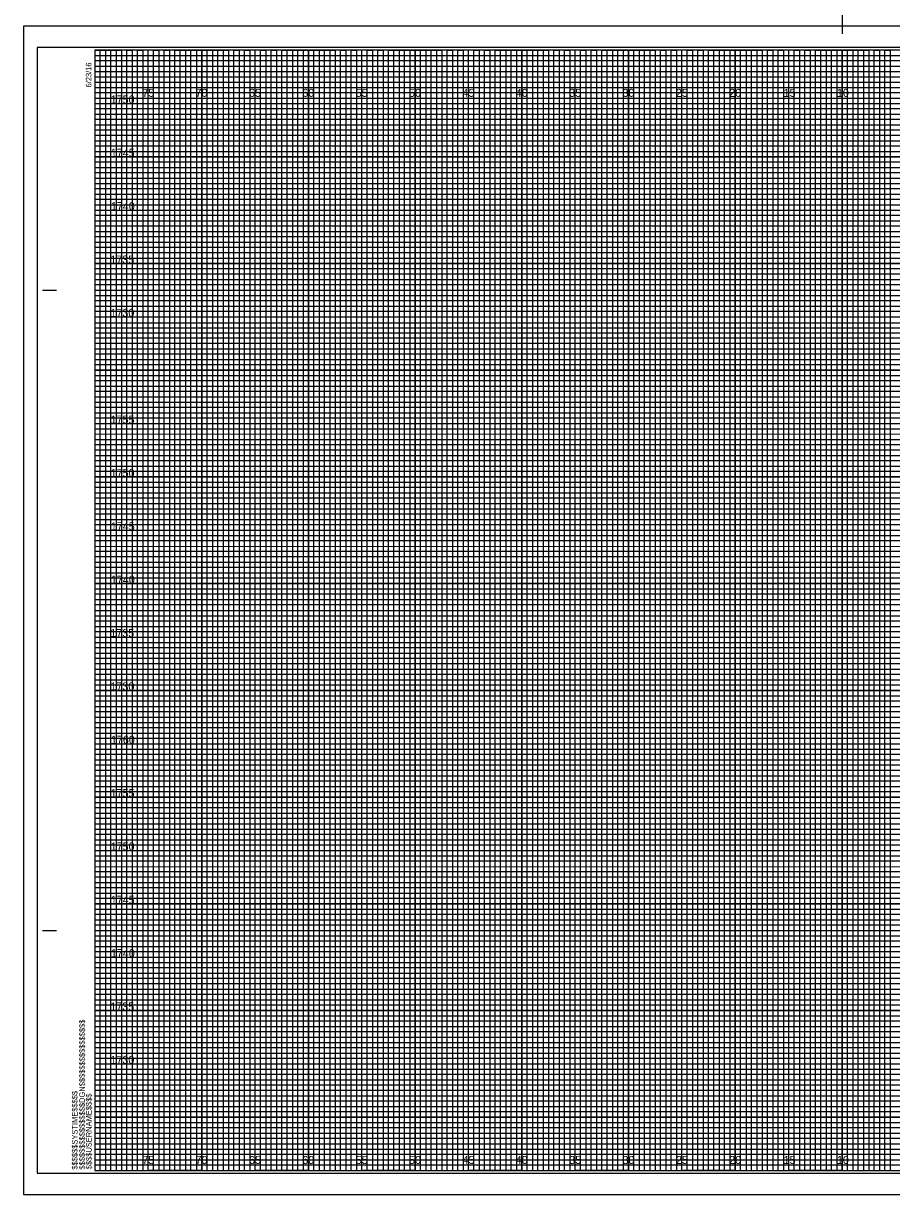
# Model space of a CAD drawing. Extents: x -7 to 162, y -2 to 327.
# Drawn here: x -6.7 to 74.6, y -2.3 to 107.5 of the extents above; entities that cross this region are included whole.
import ezdxf

# ---------------------------------------------------------------- set-up
doc = ezdxf.new("R2010")
doc.units = 0
for name, color, linetype in [('Prop XS Elevation Labels', 7, 'Continuous'), ('Prop XS Offset Labels', 7, 'Continuous'), ('Scratch_Level_5', 7, 'Continuous'), ('Sheet Cross Section CELL', 7, 'Continuous'), ('Sheet Cross Section Grid Major CELL', 7, 'Continuous'), ('Sheet Cross Section Grid Middle CELL', 7, 'Continuous'), ('Sheet Cross Section Grid Minor 1 CELL', 7, 'Continuous'), ('Sheet Cross Section Grid Minor 2 CELL', 7, 'Continuous'), ('Sheet Cutting Line CELL', 7, 'Continuous'), ('Sheet DOT Grid CELL', 7, 'Continuous'), ('Sheet Plot Border Inside CELL', 7, 'Continuous'), ('Sheet Plot Border Outside CELL', 7, 'Continuous')]:
    doc.layers.add(name, color=color, linetype=linetype)

msp = doc.modelspace()

# ---------------------------------------------------------------- linework, layer by layer
at = {"layer": 'Scratch_Level_5'}
msp.add_line((70, 176.62), (70, 106.52), dxfattribs=at)
at = {"layer": 'Sheet Cross Section CELL'}
for p, q in [((-4.9, 82.5), (-3.65, 82.5)), ((-4.85, 82.5), (-3.6, 82.5)), ((-4.9, 22.5), (-3.65, 22.5)), ((-4.85, 22.5), (-3.6, 22.5)), ((0, 0), (0, 0)), ((0, 0), (0, 0)), ((0, 0), (0, 0)), ((0, 0), (0, 0)), ((0, 0), (0, 0)), ((0, 0), (0, 0)), ((0, 0), (0, 0))]:
    msp.add_line(p, q, dxfattribs=at)
msp.add_lwpolyline([(160, 105), (0, 105), (0, 0), (160, 0)], close=True, dxfattribs=at)
at = {"layer": 'Sheet Cross Section Grid Major CELL'}
for p, q in [((5, 105), (0, 105)), ((5, 0), (5, 105)), ((15, 105), (10, 105)), ((10, 105), (10, 0)), ((15, 0), (15, 105)), ((25, 105), (20, 105)), ((20, 105), (20, 0)), ((25, 0), (25, 105)), ((35, 105), (30, 105)), ((30, 105), (30, 0)), ((35, 0), (35, 105)), ((45, 105), (40, 105)), ((40, 105), (40, 0)), ((45, 0), (45, 105)), ((55, 105), (50, 105)), ((50, 105), (50, 0)), ((55, 0), (55, 105)), ((65, 105), (60, 105)), ((60, 105), (60, 0)), ((65, 0), (65, 105)), ((75, 105), (70, 105)), ((70, 105), (70, 0)), ((10, 0), (5, 0)), ((20, 0), (15, 0)), ((30, 0), (25, 0)), ((40, 0), (35, 0)), ((50, 0), (45, 0)), ((60, 0), (55, 0)), ((70, 0), (65, 0))]:
    msp.add_line(p, q, dxfattribs=at)
for points in [[(0, 100), (160, 100), (160, 95), (0, 95)], [(0, 90), (160, 90), (160, 85), (0, 85)], [(0, 80), (160, 80), (160, 75), (0, 75)], [(0, 70), (160, 70), (160, 65), (0, 65)], [(0, 60), (160, 60), (160, 55), (0, 55)], [(0, 50), (160, 50), (160, 45), (0, 45)], [(0, 40), (160, 40), (160, 35), (0, 35)], [(0, 30), (160, 30), (160, 25), (0, 25)], [(0, 20), (160, 20), (160, 15), (0, 15)], [(0, 10), (160, 10), (160, 5), (0, 5)]]:
    msp.add_lwpolyline(points, dxfattribs=at)
at = {"layer": 'Sheet Cross Section Grid Middle CELL'}
for points in [[(0, 105), (2.5, 105), (2.5, 0), (7.5, 0), (7.5, 105), (12.5, 105), (12.5, 0), (17.5, 0), (17.5, 105), (22.5, 105), (22.5, 0), (27.5, 0), (27.5, 105), (32.5, 105), (32.5, 0), (37.5, 0), (37.5, 105), (42.5, 105), (42.5, 0), (47.5, 0), (47.5, 105), (52.5, 105), (52.5, 0), (57.5, 0), (57.5, 105), (62.5, 105), (62.5, 0), (67.5, 0), (67.5, 105), (72.5, 105), (72.5, 0), (77.5, 0)], [(0, 102.5), (137.5, 102.5)], [(0, 92.5), (160, 92.5), (160, 97.5), (0, 97.5)], [(0, 82.5), (160, 82.5), (160, 87.5), (0, 87.5)], [(0, 72.5), (160, 72.5), (160, 77.5), (0, 77.5)], [(0, 62.5), (160, 62.5), (160, 67.5), (0, 67.5)], [(0, 52.5), (160, 52.5), (160, 57.5), (0, 57.5)], [(0, 42.5), (160, 42.5), (160, 47.5), (0, 47.5)], [(0, 32.5), (160, 32.5), (160, 37.5), (0, 37.5)], [(0, 22.5), (160, 22.5), (160, 27.5), (0, 27.5)], [(0, 12.5), (160, 12.5), (160, 17.5), (0, 17.5)], [(0, 2.5), (160, 2.5), (160, 7.5), (0, 7.5)]]:
    msp.add_lwpolyline(points, dxfattribs=at)
at = {"layer": 'Sheet Cross Section Grid Minor 1 CELL'}
for p, q in [((0, 104.5), (130, 104.5)), ((130, 103.99), (0, 103.99)), ((0, 103.99), (0, 103.5)), ((0, 103.5), (130, 103.5)), ((130, 102.95), (0, 102.95)), ((0, 102.95), (0, 102)), ((0, 102), (160, 102))]:
    msp.add_line(p, q, dxfattribs=at)
for points in [[(0, 101.5), (135, 101.5), (160, 101.5), (160, 101), (0, 101)], [(0, 100.5), (160, 100.5), (160, 99.5), (0, 99.5)], [(0, 99), (160, 99), (160, 98.5), (0, 98.49)], [(0, 98), (160, 98), (160, 97), (0, 97)], [(0, 96.5), (160, 96.5), (160, 96), (0, 96)], [(0, 95.5), (160, 95.5), (160, 94.5), (0, 94.5)], [(0, 94), (160, 94), (160, 93.5), (0, 93.5)], [(0, 93), (160, 93), (160, 92), (0, 92)], [(0, 91.5), (160, 91.5), (160, 91), (0, 91)], [(0, 90.5), (160, 90.5), (160, 89.5), (0, 89.5)], [(0, 89), (160, 89), (160, 88.5), (0, 88.5)], [(0, 88), (160, 88), (160, 86.98), (160, 86.5), (160, 86), (0, 86)], [(0, 87), (160, 87), (160, 86.5), (0, 86.5)], [(0, 85.5), (160, 85.5), (160, 84.5), (0, 84.52)], [(0, 84.52), (160, 84.5), (160, 84), (0, 84)], [(0, 83.5), (160, 83.5), (160, 83), (0, 83)], [(0, 82), (160, 82), (160, 81.5), (0, 81.5)], [(0, 81), (160, 81), (160, 80.5), (0, 80.5)], [(-0.04, 79.45), (160, 79.45), (160, 78.94), (-0.04, 78.94)], [(0, 78.5), (160, 78.5), (160, 78), (0, 78)], [(0, 77), (160, 77), (160, 76.5), (0, 76.5)], [(0, 76), (160, 76), (160, 75.5), (0, 75.5)], [(0, 74.5), (160, 74.5), (160, 74), (0, 74)], [(0, 73.5), (160, 73.5), (160, 73), (0, 73)], [(0, 72), (160, 72), (160, 71.5), (0, 71.5)], [(0, 71), (160, 71), (160, 70.5), (0, 70.5)], [(0, 69.5), (160, 69.5), (160, 68.99), (0, 69)], [(0, 68.5), (160, 68.5), (160, 68), (0, 68)], [(0, 67), (160, 67), (160, 66.5), (0, 66.5)], [(0, 66), (160, 66), (160, 65.5), (0, 65.5)], [(0, 64.5), (160, 64.5), (160, 64), (0, 64)], [(0, 63.5), (160, 63.5), (160, 63), (0, 63)], [(0, 62), (160, 62), (160, 61.5), (0, 61.5)], [(0, 61), (160, 61), (160, 60.5), (0, 60.5)], [(0, 59.5), (160, 59.5), (160, 59), (0, 59)], [(0, 58.5), (160.03, 58.45), (160, 58), (0, 58)], [(0, 57), (160, 57), (160, 56.5), (0, 56.5)], [(0, 56), (160, 56), (160, 55.5), (0, 55.5)], [(0, 54.5), (160, 54.5), (160, 54), (0, 54)], [(0, 53.5), (160, 53.5), (160, 53), (0, 53)], [(0, 52), (160, 52), (160, 51.5), (0, 51.5)], [(0, 51), (160, 51), (160, 50.5), (0, 50.5)], [(0, 49.5), (160, 49.5), (160, 49), (0, 49)], [(0, 48.5), (160, 48.5), (160, 48), (0, 48)], [(0, 47), (160, 47), (160, 46.5), (0, 46.5)], [(0, 46), (160, 46), (160, 45.5), (0, 45.5)], [(0, 44.5), (160, 44.5), (160, 44), (0, 44)], [(0, 43.5), (160, 43.5), (160, 43), (0, 43)], [(0, 42), (160, 42), (160, 41.5), (0, 41.5)], [(0, 41), (160, 41), (160, 40.5), (0, 40.5)], [(0, 39.5), (160, 39.5), (160, 38.99), (0, 39)], [(0, 38.5), (160, 38.5), (160, 38), (0, 38)], [(0, 37), (160, 37), (160, 36.5), (0, 36.5)], [(0, 36), (160, 36), (160, 35.5), (0, 35.5)], [(0, 34.5), (160, 34.5), (160, 34), (0, 34)], [(0, 33.5), (160, 33.5), (160, 33), (0, 33)], [(0, 32), (160, 32), (160, 31.5), (0, 31.5)], [(0, 31), (160, 31), (160, 30.5), (0, 30.5)], [(0, 29.5), (160, 29.5), (160, 29), (0, 29)], [(0, 28.5), (160.03, 28.46), (160, 28), (0, 28)], [(0, 27), (160, 27), (160, 26.5), (0, 26.5)], [(0, 26), (160, 26), (160, 25.5), (0, 25.5)], [(0, 24.5), (160, 24.5), (160, 24), (0, 24)], [(0, 23.5), (160, 23.5), (160, 23), (0, 23)], [(0, 22), (160, 22), (160, 21.5), (0, 21.5)], [(0, 21), (160, 21), (160, 20.5), (0, 20.5)], [(0, 19.5), (160, 19.5), (160, 19), (0, 19)], [(0, 18.5), (160, 18.5), (160, 18), (0, 18)], [(0, 17), (160, 17), (160, 16.5), (0, 16.5)], [(0, 16), (160, 16), (160, 15.5), (0, 15.5)], [(0, 14.5), (160, 14.5), (160, 14), (0, 14)], [(0, 13.5), (160, 13.5), (160, 13), (0, 13)], [(0, 12), (160, 12), (160, 11.5), (0, 11.5)], [(0, 11), (160, 11), (160, 10.5), (0, 10.5)], [(0, 9.5), (160, 9.5), (160, 9), (0, 9)], [(0, 8.5), (160, 8.5), (160, 8), (0, 8)], [(0, 7), (160, 7), (160, 6.5), (0, 6.5)], [(0, 6), (160, 6), (160, 5.5), (0, 5.5)], [(0, 4.5), (160, 4.5), (160, 4), (0, 4)], [(0, 3.5), (160, 3.5), (160, 3), (0, 3)], [(0, 2), (160, 2), (160, 1.5), (0, 1.5)], [(0, 1), (160, 1), (160, 0.5), (0, 0.5)]]:
    msp.add_lwpolyline(points, dxfattribs=at)
at = {"layer": 'Sheet Cross Section Grid Minor 2 CELL'}
for points in [[(0, 0), (0.5, 0), (0.5, 105), (1, 105), (1, 0)], [(1, 0), (1.5, 0), (1.5, 105), (2, 105), (2, 0)], [(2.5, 0), (3, 0), (3, 105), (3.5, 105), (3.5, 0)], [(3.5, 0), (4, 0), (4, 105), (4.5, 105), (4.5, 0)], [(5, 0), (5.5, 0), (5.5, 105), (6, 105), (6, 0)], [(6, 0), (6.5, 0), (6.5, 105), (7, 105), (7, 0)], [(7.5, 0), (8, 0), (8, 105), (8.5, 105), (8.5, 0)], [(8.5, 0), (9, 0), (9, 105), (9.5, 105), (9.5, 0)], [(10, 0), (10.5, 0), (10.5, 105), (11, 105), (11, 0)], [(11, 0), (11.5, 0), (11.5, 105), (12, 105), (12, 0)], [(12.5, 0), (13, 0), (13, 105), (13.5, 105), (13.5, 0)], [(13.5, 0), (14, 0), (14, 105), (14.5, 105), (14.5, 0)], [(15, 0), (15.5, 0), (15.5, 105), (16, 105), (16, 0)], [(16, 0), (16.5, 0), (16.5, 105), (17, 105), (17, 0)], [(17.5, 0), (18, 0), (18, 105), (18.5, 105), (18.5, 0)], [(18.5, 0), (19, 0), (19, 105), (19.5, 105), (19.5, 0)], [(20, 0), (20.5, 0), (20.5, 105), (21, 105), (21, 0)], [(21, 0), (21.5, 0), (21.5, 105), (22, 105), (22, 0)], [(22.5, 0), (23, 0), (23, 105), (23.5, 105), (23.5, 0)], [(23.5, 0), (24, 0), (24, 105), (24.5, 105), (24.5, 0)], [(25, 0), (25.5, 0), (25.5, 105), (26, 105), (26, 0)], [(26, 0), (26.5, 0), (26.5, 105), (27, 105), (27, 0)], [(27.5, 0), (28, 0), (28, 105), (28.5, 105), (28.5, 0)], [(28.5, 0), (29, 0), (29, 105), (29.5, 105), (29.5, 0)], [(30, 0), (30.5, 0), (30.5, 105), (31, 105), (31, 0)], [(31, 0), (31.5, 0), (31.5, 105), (32, 105), (32, 0)], [(32.5, 0), (33, 0), (33, 105), (33.5, 105), (33.5, 0)], [(33.5, 0), (34, 0), (34, 105), (34.5, 105), (34.5, 0)], [(35, 0), (35.5, 0), (35.5, 105), (36, 105), (36, 0)], [(36, 0), (36.5, 0), (36.5, 105), (37, 105), (37, 0)], [(37.5, 0), (38, 0), (38, 105), (38.5, 105), (38.5, 0)], [(38.5, 0), (39, 0), (39, 105), (39.5, 105), (39.5, 0)], [(40, 0), (40.5, 0), (40.5, 105), (41, 105), (41, 0)], [(41, 0), (41.5, 0), (41.5, 105), (42, 105), (42, 0)], [(42.5, 0), (43, 0), (43, 105), (43.5, 105), (43.5, 0)], [(43.5, 0), (44, 0), (44, 105), (44.5, 105), (44.5, 0)], [(45, 0), (45.5, 0), (45.5, 105), (46, 105), (46, 0)], [(46, 0), (46.5, 0), (46.5, 105), (47, 105), (47, 0)], [(47.5, 0), (48, 0), (48, 105), (48.5, 105), (48.5, 0)], [(48.5, 0), (49, 0), (49, 105), (49.5, 105), (49.5, 0)], [(50, 0), (50.5, 0), (50.5, 105), (51, 105), (51, 0)], [(51, 0), (51.5, 0), (51.5, 105), (52, 105), (52, 0)], [(52.5, 0), (53, 0), (53, 105), (53.5, 105), (53.5, 0)], [(53.5, 0), (54, 0), (54, 105), (54.5, 105), (54.5, 0)], [(55, 0), (55.5, 0), (55.5, 105), (56, 105), (56, 0)], [(56, 0), (56.5, 0), (56.5, 105), (57, 105), (57, 0)], [(57.5, 0), (58, 0), (58, 105), (58.5, 105), (58.5, 0)], [(58.5, 0), (59, 0), (59, 105), (59.5, 105), (59.5, 0)], [(60, 0), (60.5, 0), (60.5, 105), (61, 105), (61, 0)], [(61, 0), (61.5, 0), (61.5, 105), (62, 105), (62, 0)], [(62.5, 0), (63, 0), (63, 105), (63.5, 105), (63.5, 0)], [(63.5, 0), (64, 0), (64, 105), (64.5, 105), (64.5, 0)], [(65, 0), (65.5, 0), (65.5, 105), (66, 105), (66, 0)], [(66, 0), (66.5, 0), (66.5, 105), (67, 105), (67, 0)], [(67.5, 0), (68, 0), (68, 105), (68.5, 105), (68.5, 0)], [(68.5, 0), (69, 0), (69, 105), (69.5, 105), (69.5, 0)], [(70, 0), (70.5, 0), (70.5, 105), (71, 105), (71, 0)], [(71, 0), (71.5, 0), (71.5, 105), (72, 105), (72, 0)], [(72.5, 0), (73, 0), (73, 105), (73.5, 105), (73.5, 0)], [(73.5, 0), (74, 0), (74, 105), (74.5, 105), (74.5, 0)]]:
    msp.add_lwpolyline(points, dxfattribs=at)
at = {"layer": 'Sheet Cutting Line CELL'}
for p, q in [((161.65, 107.25), (-6.7, 107.25)), ((-6.7, 107.25), (-6.7, -2.25)), ((-6.7, -2.25), (161.65, -2.25))]:
    msp.add_line(p, q, dxfattribs=at)
at = {"layer": 'Sheet DOT Grid CELL'}
for p, q in [((5, 0), (5, 105)), ((10, 0), (10, 105)), ((15, 0), (15, 105)), ((20, 0), (20, 105)), ((25, 0), (25, 105)), ((30, 0), (30, 105)), ((35, 0), (35, 105)), ((40, 0), (40, 105)), ((45, 0), (45, 105)), ((50, 0), (50, 105)), ((55, 0), (55, 105)), ((60, 0), (60, 105)), ((65, 0), (65, 105)), ((70, 0), (70, 105)), ((0, 100), (160, 100)), ((0, 95), (160, 95)), ((0, 90), (160, 90)), ((0, 85), (160, 85)), ((0, 80), (160, 80)), ((0, 75), (160, 75)), ((0, 70), (160, 70)), ((0, 65), (160, 65)), ((0, 60), (160, 60)), ((0, 55), (160, 55)), ((0, 50), (160, 50)), ((0, 45), (160, 45)), ((0, 40), (160, 40)), ((0, 35), (160, 35)), ((0, 30), (160, 30)), ((0, 25), (160, 25)), ((0, 20), (160, 20)), ((0, 15), (160, 15)), ((0, 10), (160, 10)), ((0, 5), (160, 5))]:
    msp.add_line(p, q, dxfattribs=at)
at = {"layer": 'Sheet Plot Border Inside CELL'}
msp.add_lwpolyline([(-5.4, -0.25), (161.2, -0.25), (161.2, 105.25), (-5.4, 105.25)], close=True, dxfattribs=at)
at = {"layer": 'Sheet Plot Border Outside CELL'}
msp.add_lwpolyline([(-6.7, -2.25), (161.65, -2.25), (161.65, 107.25), (-6.7, 107.25)], close=True, dxfattribs=at)

# ---------------------------------------------------------------- texts
at = {"layer": 'Prop XS Elevation Labels'}
for s, p in [('1750', (1.48, 100)), ('1745', (1.49, 95)), ('1740', (1.5, 90)), ('1735', (1.45, 85)), ('1730', (1.46, 80)), ('1755', (1.47, 70)), ('1750', (1.48, 65)), ('1745', (1.49, 60)), ('1740', (1.5, 55)), ('1735', (1.45, 50)), ('1730', (1.46, 45)), ('1760', (1.5, 40)), ('1755', (1.47, 35)), ('1750', (1.48, 30)), ('1745', (1.49, 25)), ('1740', (1.5, 20)), ('1735', (1.45, 15)), ('1730', (1.46, 10))]:
    msp.add_text(s, height=0.75, dxfattribs=at).set_placement(p)
at = {"layer": 'Prop XS Offset Labels'}
for s, p in [('75', (4.44, 100.62)), ('70', (9.43, 100.62)), ('65', (14.44, 100.62)), ('60', (19.43, 100.62)), ('55', (24.44, 100.62)), ('50', (29.43, 100.62)), ('45', (34.44, 100.62)), ('40', (39.43, 100.62)), ('35', (44.44, 100.62)), ('30', (49.43, 100.62)), ('25', (54.44, 100.62)), ('20', (59.43, 100.62)), ('15', (64.53, 100.62)), ('10', (69.52, 100.62)), ('75', (4.44, 0.62)), ('70', (9.43, 0.62)), ('65', (14.44, 0.62)), ('60', (19.43, 0.62)), ('55', (24.44, 0.62)), ('50', (29.43, 0.62)), ('45', (34.44, 0.62)), ('40', (39.43, 0.62)), ('35', (44.44, 0.62)), ('30', (49.43, 0.62)), ('25', (54.44, 0.62)), ('20', (59.43, 0.62)), ('15', (64.53, 0.62)), ('10', (69.52, 0.62))]:
    msp.add_text(s, height=0.75, dxfattribs=at).set_placement(p)
at = {"layer": 'Sheet Cross Section CELL'}
for s, p in [('6/23/16', (-0.33, 101.5)), ('$$$$$$$$$$$$$$$$DGN$$$$$$$$$$$$$$$$', (-0.94, 0.09)), ('$$$$$$SYSTIME$$$$$', (-1.63, 0.09)), ('$$$$USERNAME$$$$', (-0.31, 0.12))]:
    msp.add_text(s, height=0.525, rotation=90, dxfattribs=at).set_placement(p)

doc.saveas('drawing.dxf')
